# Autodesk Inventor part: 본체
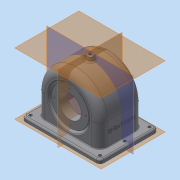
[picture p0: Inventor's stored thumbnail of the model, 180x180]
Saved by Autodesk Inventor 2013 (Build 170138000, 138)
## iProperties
Created: 2015-09
Part Number: 본체
Material: 일반
Document SubType Name: Modeling
Designer: Administrator
Density: 1 g/cm^3
Author: Administrator
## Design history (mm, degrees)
sketch "스케치1"
  geometry: L1 (-70, -52)-(70, -52); L2 (70, -52)-(70, 52); L3 (70, 52)-(-70, 52); L4 (-70, 52)-(-70, -52); 3 further points
  constraints: 8 end point, 2 midpoint, 2 parallel, 1 horizontal, 1 horizontal alignment, 1 perpendicular, 1 vertical alignment
  dimensions: "d0" = 140 distance of L2.end L3.end; "d2" = 104 distance of L1.end L2.end
extrude "돌출1" new body sketch "스케치1" distance "d3" = 7; taper "d4" = 0 deg
sketch "스케치2"
  geometry: L1 (70, 7)-(-70, 7) reference; L2 (51, 7)-(51, 47); L3 (-51, 7)-(-51, 47); L4 (51, 47)-(-51, 47); L5 (70, 0)-(-70, 0) reference; L6 (-56, 47)-(-56, 41.907); L7 (-56, 41.907)-(-56, 7); L8 (56, 47)-(56, 7); A1 r 51 centre (0, 47) between (51, 47) and (-51, 47); A2 r 56 centre (0, 47) between (56, 47) and (-56, 47); 3 further points
  constraints: 12 end point, 5 perpendicular, 4 point on circle, 4 point on line, 3 tangent, 2 centre point, 2 midpoint, 1 parallel, 1 vertical alignment
  dimensions: "d6" = 51 radius of A1; "d7" = 47 distance from line of L3.end L5; "d26" = 5 radial gap between concentric circles of A2 A1
extrude "돌출5" join sketch "스케치2" stored distance "d27" = 77; taper "d28" = 0 deg
node "작업 평면2"
sketch "스케치7"
  geometry: C1 r 20 at (0, -47); A1 r 56 centre (0, -47) between (-56, -47) and (56, -47) reference; 1 further point
  constraints: 1 centre point, 1 coincident
  dimensions: "d34" = 40 diameter of C1
extrude "돌출7" cut sketch "스케치7" stored distance "d36" = 77; taper "d37" = 0 deg
sketch "스케치8"
  geometry: L1 (51, 7)-(51, 47) reference; L2 (70, 7)-(-70, 7) reference; L3 (-51, 7)-(-51, 47) reference; A1 r 51 centre (0, 47) between (51, 47) and (-51, 47) reference; 2 further points
extrude "돌출8" cut sketch "스케치8" stored distance "d38" = 67; taper "d39" = 0 deg
sketch "스케치10"
  geometry: C1 r 20 at (0, -47) reference; C2 r 31 at (0, -47); 1 further point
  constraints: 1 centre point, 1 coincident
  dimensions: "d41" = 62 diameter of C2
extrude "돌출9" join sketch "스케치10" distance "d44" = 10; taper "d45" = 0 deg
node "작업 평면4"
sketch "스케치11"
  geometry: L1 (-35.5, 132)-(-35.5, -22) reference; L2 (-35.5, 88.426)-(-19.5, 75); L3 (-19.5, 75)-(-19.5, 47); L4 (-19.5, 47)-(-35.5, 47); L5 (52, 0)-(-52, 0) reference; 1 further point
  constraints: 6 end point, 2 point on line, 1 perpendicular, 1 vertical alignment
  dimensions: "d48" = 50 deg angle of L3 L2; "d49" = 47 distance from line of L4.end L5; "d50" = 16 distance of L3.end L4.end; "d51" = 56 diameter of L2.end L4
revolve "회전1" sketch "스케치11" stored, may be unused: angle "d52" = 90 deg
sketch "스케치13"
  geometry: L1 (-33.5, 86.747)-(-19.5, 75) reference; L2 (-38.5, 9.584)-(-35.5, 12.101); L3 (-38.5, 103)-(-38.5, 47) reference; L4 (-33.5, 47)-(33.5, 47) reference; L5 (-33.5, 47)-(-33.5, 47) reference; L6 (33.5, 47)-(-33.5, 47) reference; L7 (33.5, 47)-(33.5, 47) reference; L8 (-38.5, 84.416)-(-24.756, 72.883); L9 (-24.756, 72.883)-(-24.756, 47); L10 (-38.5, 47)-(-38.5, 84.416); L11 (-38.5, 47)-(-24.756, 47); 1 further point
  constraints: 11 end point, 2 point on line, 1 collinear, 1 parallel, 1 perpendicular
  dimensions: "d60" = 5 distance from line of L1 L8.end
revolve "회전2" sketch "스케치13" stored, may be unused: angle "d61" = 90 deg
node "작업 평면5"
sketch "스케치14"
  geometry: C1 r 33 at (0, 47); A1 r 56 centre (0, 47) between (56, 47) and (-56, 47) reference; 1 further point
  constraints: 1 centre point, 1 coincident
  dimensions: "d63" = 66 diameter of C1
extrude "돌출11" join sketch "스케치14" stored distance "d65" = 5; taper "d66" = 0 deg
sketch "스케치15"
  geometry: C1 r 33 at (0, 0) reference; A1 r 28 centre (0, 0) between (0, 28) and (-28, 0); 3 further points
  constraints: 4 point on circle, 1 centre point, 1 coincident
  dimensions: "d67" = 56 diameter of A1
hole "구멍2" sketch "스케치15" at (0, 28), (-28, 0), (0, -28), (28, 0) diameter "d69" = 2.459; stored, may be unused: countersink angle "d73" = 90 deg, drill point angle "d75" = 118 deg; dims "d70" = 7, "d71" = 4, "d72" = 2, "d74" = 9
sketch "스케치16"
  geometry: C1 r 20 at (0, 0); A1 r 56 centre (0, 0) between (56, 0) and (-56, 0) reference; 1 further point
  constraints: 1 centre point, 1 coincident
  dimensions: "d76" = 40 diameter of C1
extrude "돌출12" cut sketch "스케치16" stored distance "d78" = 5; taper "d79" = 0 deg
fillet "모깎기1" dims "d80" = 0.5
sketch "스케치19"
  geometry: L1 (-2.826, 16.342)-(-2.826, 42.658); L2 (-2.826, 42.658)-(36.826, 42.658); L3 (36.826, 42.658)-(36.826, 16.342); L4 (36.826, 16.342)-(-2.826, 16.342); L5 (36.826, 16.342)-(-2.826, 42.658); L6 (-85, 29.5)-(69, 29.5) reference; L7 (0, -9)-(40, -9) reference; L8 (47, -22.5)-(47, 81.5) reference; 2 further points
  constraints: 2 end point, 1 midpoint, 2 other
  dimensions: "d86" = 38.5 distance from line of point (17, 29.5) L7; "d87" = 30 distance from line of point (17, 29.5) L8
feature "엠보싱1" sketch "스케치19" dims "d0" = 140, "d2" = 104, "d6" = 51, "d7" = 47, "d26" = 5, "d88" = 0.5, "d89" = 0
sketch "스케치20"
  geometry: L1 (-70, 52)-(-70, -52) reference; L2 (70, 52)-(-70, 52) reference; C1 r 2.5 at (-62, 44); C2 r 2.5 at (-62, 0); C3 r 2.5 at (-62, -44); 1 further point
  constraints: 3 centre point, 2 vertical alignment
  dimensions: "d90" = 5 diameter of C1; "d92" = 5 diameter of C2; "d93" = 44 distance of C1.centre C2.centre; "d94" = 44 distance of C2.centre C3.centre; "d95" = 8 distance from line of L1 C1.centre; "d96" = 8 distance from line of L2 C1.centre; "d97" = 5 diameter of C3
extrude "돌출13" cut sketch "스케치20" stored distance "d98" = 49; taper "d99" = 0 deg
fillet "모깎기4" dims "d100" = 7
sketch "스케치21"
  geometry: C1 r 31 at (0, 0) reference; A1 r 24 centre (0, 0) between (0, 24) and (-24, 0); 3 further points
  constraints: 4 point on circle, 1 centre point, 1 coincident
  dimensions: "d101" = 48 diameter of A1
hole "구멍3" sketch "스케치21" at (0, -24), (-24, 0), (24, 0), (0, 24) diameter "d103" = 2.459; stored, may be unused: countersink angle "d107" = 90 deg, drill point angle "d109" = 118 deg; dims "d104" = 6, "d105" = 4, "d106" = 2, "d108" = 8
fillet "모깎기6" dims "d111" = 3
fillet "모깎기7" dims "d112" = 3
sketch "스케치22"
  geometry: L1 (-38.5, 103)-(38.5, 103) reference; L2 (-6, 110)-(0, 110); L3 (0, 110)-(0, 98); L4 (0, 98)-(-8.116, 98); L5 (-33.5, 98)-(33.5, 98) reference; L6 (-8.116, 98)-(-6, 110); L7 (45, 0)-(-45, 0) reference; 1 further point
  constraints: 8 end point, 2 vertical alignment, 1 horizontal alignment, 1 midpoint, 1 parallel
  dimensions: "d114" = 12 diameter of L2.start L3; "d116" = 100 deg angle of L2 L6; "d118" = 110 distance from line of L2.start L7
fillet "모깎기9" dims "d119" = 9
fillet "모깎기10" dims "d120" = 14
fillet "모깎기11" dims "d121" = 1
revolve "회전3" stored, may be unused: angle "d122" = 90 deg
fillet "모깎기12" dims "d123" = 3
sketch "스케치23"
  geometry: 2 further points
  constraints: 1 coincident
hole "구멍4" sketch "스케치23" at (0, 0) diameter "d124" = 4.134; stored, may be unused: countersink angle "d128" = 90 deg, drill point angle "d130" = 0 deg; dims "d125" = 15, "d126" = 4, "d127" = 2, "d129" = 15
chamfer "모따기1" distance "d131" = 1; stored, may be unused: second distance "d132" = 2, angle "d133" = 45 deg
node "솔리드1"
mirror "대칭1"
node "투영된 루프1"
other parameters: "d47" = -84, "d62" = -3
